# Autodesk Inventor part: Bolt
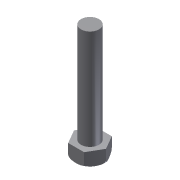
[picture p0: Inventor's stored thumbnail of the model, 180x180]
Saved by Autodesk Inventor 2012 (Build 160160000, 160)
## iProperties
Shininess: 77.0
Length Units: 11269
Angle Units: 11279
Time Units: 11290
Mass Units: 11283
Length Display Precision: 3
Angle Display Precision: 2
Created: 2002-02
Part Number: Bolt
Document SubType Name: Modeling
Designer: ***
Density: 1 g/cm^3
Material: Default
Density: 0.0
Volumn: 0.0
Area: 0.0
PropertySet Name: Model Information
Control State: 0
Master: False
Checked Out: False
Author: ***
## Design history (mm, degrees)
sketch "Sketch1"
  geometry: C1 r 4 at (0, 0)
  constraints: 1 centre point
  dimensions: "d0" = 8 diameter of C1
extrude "Extrusion1" new body sketch "Sketch1" stored distance "d1" = 3.5; taper "d2" = 0 deg
fillet "Fillet1" dims "d3" = 1
sketch "Sketch2"
  geometry: L1 (4, 0)-(2, -3.464); L2 (2, -3.464)-(-2, -3.464); L3 (-2, -3.464)-(-4, 0); L4 (-4, 0)-(-2, 3.464); L5 (-2, 3.464)-(2, 3.464); L6 (2, 3.464)-(4, 0); 2 further points
  constraints: 12 end point, 1 coincident, 11 other
extrude "Extrusion2" sketch "Sketch2" stored distance "d4" = 3.5; taper "d5" = 0 deg
sketch "Sketch3"
  geometry: C1 r 2.25 at (0, 0)
  constraints: 1 centre point
  dimensions: "d6" = 4.5 diameter of C1
extrude "Extrusion3" join sketch "Sketch3" distance "d7" = 25; taper "d8" = 0 deg
body "Solid1"
